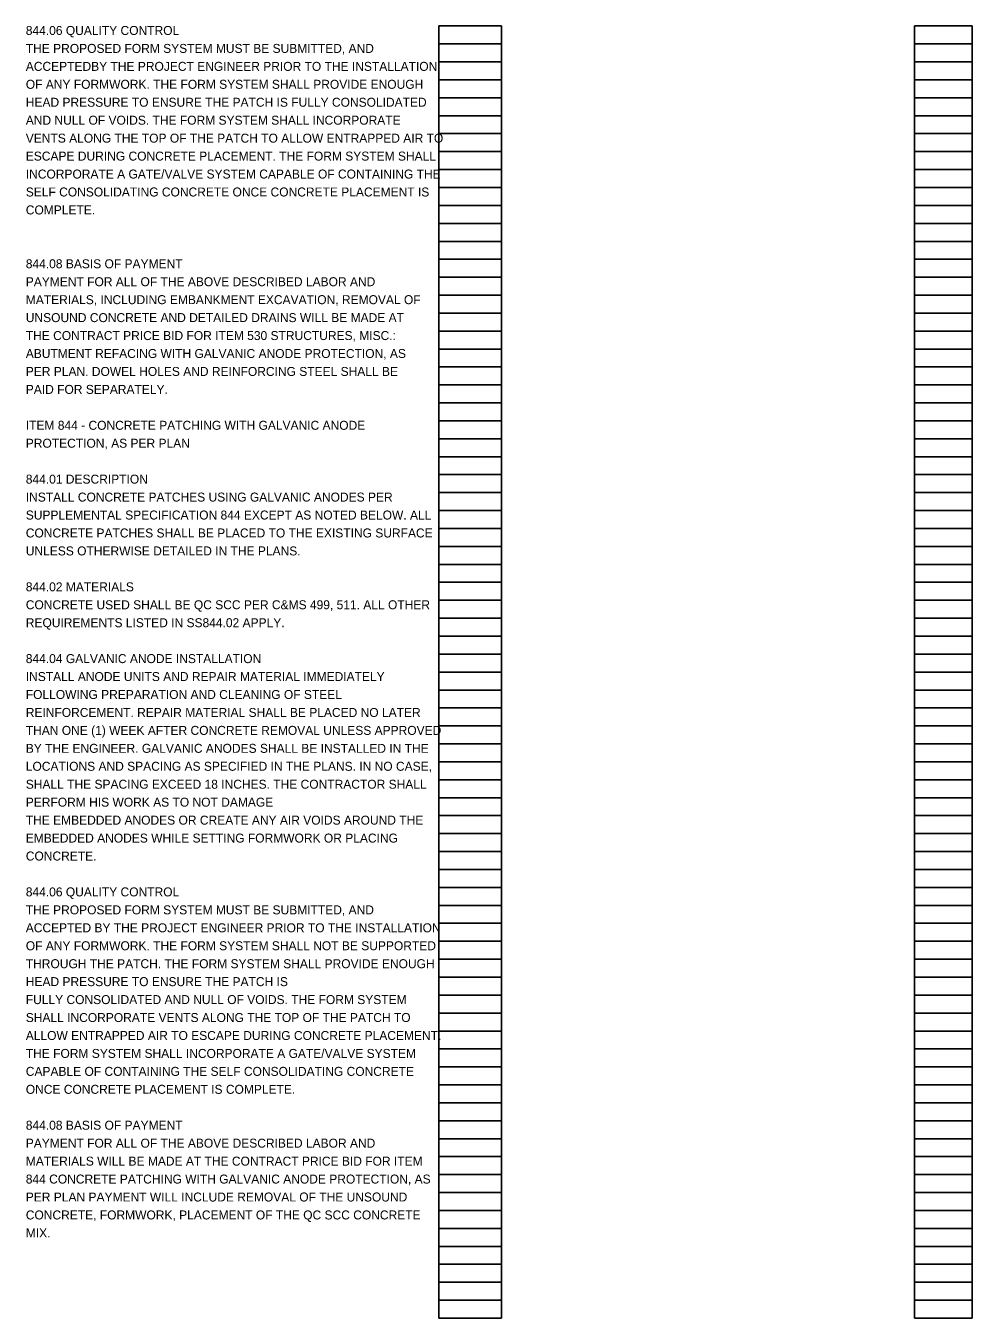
# Model space of a CAD drawing. Extents: x 0 to 66.4, y 0 to 28.8.
# Drawn here: x 51.65 to 66.41, y 0.98 to 21.14 of the extents above; entities that cross this region are included whole.
import ezdxf

# ---------------------------------------------------------------- set-up
doc = ezdxf.new("R2010")
doc.units = 0
doc.layers.add('SH_Data', color=7, linetype='Continuous')
doc.layers.add('SH_Text', color=7, linetype='Continuous')

msp = doc.modelspace()

# ---------------------------------------------------------------- linework, layer by layer
at = {"layer": 'SH_Data'}
for p, q in [((58.094, 0.98), (58.094, 21.14)), ((58.094, 21.14), (59.074, 21.14)), ((58.094, 0.98), (58.094, 21.14)), ((58.094, 21.14), (59.074, 21.14)), ((59.074, 0.98), (59.074, 21.14)), ((59.074, 0.98), (59.074, 21.14)), ((65.514, 0.98), (65.514, 21.14)), ((65.514, 21.14), (66.414, 21.14)), ((65.514, 0.98), (65.514, 21.14)), ((65.514, 21.14), (66.414, 21.14)), ((66.414, 0.98), (66.414, 21.14)), ((66.414, 0.98), (66.414, 21.14)), ((58.094, 20.86), (59.074, 20.86)), ((58.094, 20.86), (59.074, 20.86)), ((65.514, 20.86), (66.414, 20.86)), ((65.514, 20.86), (66.414, 20.86)), ((58.094, 20.58), (59.074, 20.58)), ((58.094, 20.58), (59.074, 20.58)), ((65.514, 20.58), (66.414, 20.58)), ((65.514, 20.58), (66.414, 20.58)), ((58.094, 20.3), (59.074, 20.3)), ((58.094, 20.3), (59.074, 20.3)), ((65.514, 20.3), (66.414, 20.3)), ((65.514, 20.3), (66.414, 20.3)), ((58.094, 20.02), (59.074, 20.02)), ((58.094, 20.02), (59.074, 20.02)), ((65.514, 20.02), (66.414, 20.02)), ((65.514, 20.02), (66.414, 20.02)), ((58.094, 19.74), (59.074, 19.74)), ((58.094, 19.74), (59.074, 19.74)), ((65.514, 19.74), (66.414, 19.74)), ((65.514, 19.74), (66.414, 19.74)), ((58.094, 19.46), (59.074, 19.46)), ((58.094, 19.46), (59.074, 19.46)), ((65.514, 19.46), (66.414, 19.46)), ((65.514, 19.46), (66.414, 19.46)), ((58.094, 19.18), (59.074, 19.18)), ((58.094, 19.18), (59.074, 19.18)), ((65.514, 19.18), (66.414, 19.18)), ((65.514, 19.18), (66.414, 19.18)), ((58.094, 18.9), (59.074, 18.9)), ((58.094, 18.9), (59.074, 18.9)), ((65.514, 18.9), (66.414, 18.9)), ((65.514, 18.9), (66.414, 18.9)), ((58.094, 18.62), (59.074, 18.62)), ((58.094, 18.62), (59.074, 18.62)), ((65.514, 18.62), (66.414, 18.62)), ((65.514, 18.62), (66.414, 18.62)), ((58.094, 18.34), (59.074, 18.34)), ((58.094, 18.34), (59.074, 18.34)), ((65.514, 18.34), (66.414, 18.34)), ((65.514, 18.34), (66.414, 18.34)), ((58.094, 18.06), (59.074, 18.06)), ((58.094, 18.06), (59.074, 18.06)), ((65.514, 18.06), (66.414, 18.06)), ((65.514, 18.06), (66.414, 18.06)), ((58.094, 17.78), (59.074, 17.78)), ((58.094, 17.78), (59.074, 17.78)), ((65.514, 17.78), (66.414, 17.78)), ((65.514, 17.78), (66.414, 17.78)), ((58.094, 17.5), (59.074, 17.5)), ((58.094, 17.5), (59.074, 17.5)), ((65.514, 17.5), (66.414, 17.5)), ((65.514, 17.5), (66.414, 17.5)), ((58.094, 17.22), (59.074, 17.22)), ((58.094, 17.22), (59.074, 17.22)), ((65.514, 17.22), (66.414, 17.22)), ((65.514, 17.22), (66.414, 17.22)), ((58.094, 16.94), (59.074, 16.94)), ((58.094, 16.94), (59.074, 16.94)), ((65.514, 16.94), (66.414, 16.94)), ((65.514, 16.94), (66.414, 16.94)), ((58.094, 16.66), (59.074, 16.66)), ((58.094, 16.66), (59.074, 16.66)), ((65.514, 16.66), (66.414, 16.66)), ((65.514, 16.66), (66.414, 16.66)), ((58.094, 16.38), (59.074, 16.38)), ((58.094, 16.38), (59.074, 16.38)), ((65.514, 16.38), (66.414, 16.38)), ((65.514, 16.38), (66.414, 16.38)), ((58.094, 16.1), (59.074, 16.1)), ((58.094, 16.1), (59.074, 16.1)), ((65.514, 16.1), (66.414, 16.1)), ((65.514, 16.1), (66.414, 16.1)), ((58.094, 15.82), (59.074, 15.82)), ((58.094, 15.82), (59.074, 15.82)), ((65.514, 15.82), (66.414, 15.82)), ((65.514, 15.82), (66.414, 15.82)), ((58.094, 15.54), (59.074, 15.54)), ((58.094, 15.54), (59.074, 15.54)), ((65.514, 15.54), (66.414, 15.54)), ((65.514, 15.54), (66.414, 15.54)), ((58.094, 15.26), (59.074, 15.26)), ((58.094, 15.26), (59.074, 15.26)), ((65.514, 15.26), (66.414, 15.26)), ((65.514, 15.26), (66.414, 15.26)), ((58.094, 14.98), (59.074, 14.98)), ((58.094, 14.98), (59.074, 14.98)), ((65.514, 14.98), (66.414, 14.98)), ((65.514, 14.98), (66.414, 14.98)), ((58.094, 14.7), (59.074, 14.7)), ((58.094, 14.7), (59.074, 14.7)), ((65.514, 14.7), (66.414, 14.7)), ((65.514, 14.7), (66.414, 14.7)), ((58.094, 14.42), (59.074, 14.42)), ((58.094, 14.42), (59.074, 14.42)), ((65.514, 14.42), (66.414, 14.42)), ((65.514, 14.42), (66.414, 14.42)), ((58.094, 14.14), (59.074, 14.14)), ((58.094, 14.14), (59.074, 14.14)), ((65.514, 14.14), (66.414, 14.14)), ((65.514, 14.14), (66.414, 14.14)), ((58.094, 13.86), (59.074, 13.86)), ((58.094, 13.86), (59.074, 13.86)), ((65.514, 13.86), (66.414, 13.86)), ((65.514, 13.86), (66.414, 13.86)), ((58.094, 13.58), (59.074, 13.58)), ((58.094, 13.58), (59.074, 13.58)), ((65.514, 13.58), (66.414, 13.58)), ((65.514, 13.58), (66.414, 13.58)), ((58.094, 13.3), (59.074, 13.3)), ((58.094, 13.3), (59.074, 13.3)), ((65.514, 13.3), (66.414, 13.3)), ((65.514, 13.3), (66.414, 13.3)), ((58.094, 13.02), (59.074, 13.02)), ((58.094, 13.02), (59.074, 13.02)), ((65.514, 13.02), (66.414, 13.02)), ((65.514, 13.02), (66.414, 13.02)), ((58.094, 12.74), (59.074, 12.74)), ((58.094, 12.74), (59.074, 12.74)), ((65.514, 12.74), (66.414, 12.74)), ((65.514, 12.74), (66.414, 12.74)), ((58.094, 12.46), (59.074, 12.46)), ((58.094, 12.46), (59.074, 12.46)), ((65.514, 12.46), (66.414, 12.46)), ((65.514, 12.46), (66.414, 12.46)), ((58.094, 12.18), (59.074, 12.18)), ((58.094, 12.18), (59.074, 12.18)), ((65.514, 12.18), (66.414, 12.18)), ((65.514, 12.18), (66.414, 12.18)), ((58.094, 11.9), (59.074, 11.9)), ((58.094, 11.9), (59.074, 11.9)), ((65.514, 11.9), (66.414, 11.9)), ((65.514, 11.9), (66.414, 11.9)), ((58.094, 11.62), (59.074, 11.62)), ((58.094, 11.62), (59.074, 11.62)), ((65.514, 11.62), (66.414, 11.62)), ((65.514, 11.62), (66.414, 11.62)), ((58.094, 11.34), (59.074, 11.34)), ((58.094, 11.34), (59.074, 11.34)), ((65.514, 11.34), (66.414, 11.34)), ((65.514, 11.34), (66.414, 11.34)), ((58.094, 11.06), (59.074, 11.06)), ((58.094, 11.06), (59.074, 11.06)), ((65.514, 11.06), (66.414, 11.06)), ((65.514, 11.06), (66.414, 11.06)), ((58.094, 10.78), (59.074, 10.78)), ((58.094, 10.78), (59.074, 10.78)), ((65.514, 10.78), (66.414, 10.78)), ((65.514, 10.78), (66.414, 10.78)), ((58.094, 10.5), (59.074, 10.5)), ((58.094, 10.5), (59.074, 10.5)), ((65.514, 10.5), (66.414, 10.5)), ((65.514, 10.5), (66.414, 10.5)), ((58.094, 10.22), (59.074, 10.22)), ((58.094, 10.22), (59.074, 10.22)), ((65.514, 10.22), (66.414, 10.22)), ((65.514, 10.22), (66.414, 10.22)), ((58.094, 9.94), (59.074, 9.94)), ((58.094, 9.94), (59.074, 9.94)), ((65.514, 9.94), (66.414, 9.94)), ((65.514, 9.94), (66.414, 9.94)), ((58.094, 9.66), (59.074, 9.66)), ((58.094, 9.66), (59.074, 9.66)), ((65.514, 9.66), (66.414, 9.66)), ((65.514, 9.66), (66.414, 9.66)), ((58.094, 9.38), (59.074, 9.38)), ((58.094, 9.38), (59.074, 9.38)), ((65.514, 9.38), (66.414, 9.38)), ((65.514, 9.38), (66.414, 9.38)), ((58.094, 9.1), (59.074, 9.1)), ((58.094, 9.1), (59.074, 9.1)), ((65.514, 9.1), (66.414, 9.1)), ((65.514, 9.1), (66.414, 9.1)), ((58.094, 8.82), (59.074, 8.82)), ((58.094, 8.82), (59.074, 8.82)), ((65.514, 8.82), (66.414, 8.82)), ((65.514, 8.82), (66.414, 8.82)), ((58.094, 8.54), (59.074, 8.54)), ((58.094, 8.54), (59.074, 8.54)), ((65.514, 8.54), (66.414, 8.54)), ((65.514, 8.54), (66.414, 8.54)), ((58.094, 8.26), (59.074, 8.26)), ((58.094, 8.26), (59.074, 8.26)), ((65.514, 8.26), (66.414, 8.26)), ((65.514, 8.26), (66.414, 8.26)), ((58.094, 7.98), (59.074, 7.98)), ((58.094, 7.98), (59.074, 7.98)), ((65.514, 7.98), (66.414, 7.98)), ((65.514, 7.98), (66.414, 7.98)), ((58.094, 7.7), (59.074, 7.7)), ((58.094, 7.7), (59.074, 7.7)), ((65.514, 7.7), (66.414, 7.7)), ((65.514, 7.7), (66.414, 7.7)), ((58.094, 7.42), (59.074, 7.42)), ((58.094, 7.42), (59.074, 7.42)), ((65.514, 7.42), (66.414, 7.42)), ((65.514, 7.42), (66.414, 7.42)), ((58.094, 7.14), (59.074, 7.14)), ((58.094, 7.14), (59.074, 7.14)), ((65.514, 7.14), (66.414, 7.14)), ((65.514, 7.14), (66.414, 7.14)), ((58.094, 6.86), (59.074, 6.86)), ((58.094, 6.86), (59.074, 6.86)), ((65.514, 6.86), (66.414, 6.86)), ((65.514, 6.86), (66.414, 6.86)), ((58.094, 6.58), (59.074, 6.58)), ((58.094, 6.58), (59.074, 6.58)), ((65.514, 6.58), (66.414, 6.58)), ((65.514, 6.58), (66.414, 6.58)), ((58.094, 6.3), (59.074, 6.3)), ((58.094, 6.3), (59.074, 6.3)), ((65.514, 6.3), (66.414, 6.3)), ((65.514, 6.3), (66.414, 6.3)), ((58.094, 6.02), (59.074, 6.02)), ((58.094, 6.02), (59.074, 6.02)), ((65.514, 6.02), (66.414, 6.02)), ((65.514, 6.02), (66.414, 6.02)), ((58.094, 5.74), (59.074, 5.74)), ((58.094, 5.74), (59.074, 5.74)), ((65.514, 5.74), (66.414, 5.74)), ((65.514, 5.74), (66.414, 5.74)), ((58.094, 5.46), (59.074, 5.46)), ((58.094, 5.46), (59.074, 5.46)), ((65.514, 5.46), (66.414, 5.46)), ((65.514, 5.46), (66.414, 5.46)), ((58.094, 5.18), (59.074, 5.18)), ((58.094, 5.18), (59.074, 5.18)), ((65.514, 5.18), (66.414, 5.18)), ((65.514, 5.18), (66.414, 5.18)), ((58.094, 4.9), (59.074, 4.9)), ((58.094, 4.9), (59.074, 4.9)), ((65.514, 4.9), (66.414, 4.9)), ((65.514, 4.9), (66.414, 4.9)), ((58.094, 4.62), (59.074, 4.62)), ((58.094, 4.62), (59.074, 4.62)), ((65.514, 4.62), (66.414, 4.62)), ((65.514, 4.62), (66.414, 4.62)), ((58.094, 4.34), (59.074, 4.34)), ((58.094, 4.34), (59.074, 4.34)), ((65.514, 4.34), (66.414, 4.34)), ((65.514, 4.34), (66.414, 4.34)), ((58.094, 4.06), (59.074, 4.06)), ((58.094, 4.06), (59.074, 4.06)), ((65.514, 4.06), (66.414, 4.06)), ((65.514, 4.06), (66.414, 4.06)), ((58.094, 3.78), (59.074, 3.78)), ((58.094, 3.78), (59.074, 3.78)), ((65.514, 3.78), (66.414, 3.78)), ((65.514, 3.78), (66.414, 3.78)), ((58.094, 3.5), (59.074, 3.5)), ((58.094, 3.5), (59.074, 3.5)), ((65.514, 3.5), (66.414, 3.5)), ((65.514, 3.5), (66.414, 3.5)), ((58.094, 3.22), (59.074, 3.22)), ((58.094, 3.22), (59.074, 3.22)), ((65.514, 3.22), (66.414, 3.22)), ((65.514, 3.22), (66.414, 3.22)), ((58.094, 2.94), (59.074, 2.94)), ((58.094, 2.94), (59.074, 2.94)), ((65.514, 2.94), (66.414, 2.94)), ((65.514, 2.94), (66.414, 2.94)), ((58.094, 2.66), (59.074, 2.66)), ((58.094, 2.66), (59.074, 2.66)), ((65.514, 2.66), (66.414, 2.66)), ((65.514, 2.66), (66.414, 2.66)), ((58.094, 2.38), (59.074, 2.38)), ((58.094, 2.38), (59.074, 2.38)), ((65.514, 2.38), (66.414, 2.38)), ((65.514, 2.38), (66.414, 2.38)), ((58.094, 2.1), (59.074, 2.1)), ((58.094, 2.1), (59.074, 2.1)), ((65.514, 2.1), (66.414, 2.1)), ((65.514, 2.1), (66.414, 2.1)), ((58.094, 1.82), (59.074, 1.82)), ((58.094, 1.82), (59.074, 1.82)), ((65.514, 1.82), (66.414, 1.82)), ((65.514, 1.82), (66.414, 1.82)), ((58.094, 1.54), (59.074, 1.54)), ((58.094, 1.54), (59.074, 1.54)), ((65.514, 1.54), (66.414, 1.54)), ((65.514, 1.54), (66.414, 1.54)), ((58.094, 1.26), (59.074, 1.26)), ((58.094, 1.26), (59.074, 1.26)), ((65.514, 1.26), (66.414, 1.26)), ((65.514, 1.26), (66.414, 1.26)), ((58.094, 0.98), (59.074, 0.98)), ((58.094, 0.98), (59.074, 0.98)), ((65.514, 0.98), (66.414, 0.98)), ((65.514, 0.98), (66.414, 0.98))]:
    msp.add_line(p, q, dxfattribs=at)

# ---------------------------------------------------------------- texts
at = {"layer": 'SH_Text'}
for s, p in [('844.06 QUALITY CONTROL', (51.654, 21)), ('THE PROPOSED FORM SYSTEM MUST BE SUBMITTED, AND', (51.654, 20.72)), ('ACCEPTEDBY THE PROJECT ENGINEER PRIOR TO THE INSTALLATION', (51.654, 20.44)), ('OF ANY FORMWORK. THE FORM SYSTEM SHALL PROVIDE ENOUGH', (51.654, 20.16)), ('HEAD PRESSURE TO ENSURE THE PATCH IS FULLY CONSOLIDATED', (51.654, 19.88)), ('AND NULL OF VOIDS. THE FORM SYSTEM SHALL INCORPORATE', (51.654, 19.6)), ('VENTS ALONG THE TOP OF THE PATCH TO ALLOW ENTRAPPED AIR TO', (51.654, 19.32)), ('ESCAPE DURING CONCRETE PLACEMENT. THE FORM SYSTEM SHALL', (51.654, 19.04)), ('INCORPORATE A GATE/VALVE SYSTEM CAPABLE OF CONTAINING THE', (51.654, 18.76)), ('SELF CONSOLIDATING CONCRETE ONCE CONCRETE PLACEMENT IS', (51.654, 18.48)), ('COMPLETE.', (51.654, 18.2)), ('844.08 BASIS OF PAYMENT', (51.654, 17.36)), ('PAYMENT FOR ALL OF THE ABOVE DESCRIBED LABOR AND', (51.654, 17.08)), ('MATERIALS, INCLUDING EMBANKMENT EXCAVATION, REMOVAL OF ', (51.654, 16.8)), ('UNSOUND CONCRETE AND DETAILED DRAINS WILL BE MADE AT', (51.654, 16.52)), ('THE CONTRACT PRICE BID FOR ITEM 530 STRUCTURES, MISC.: ', (51.654, 16.24)), ('ABUTMENT REFACING WITH GALVANIC ANODE PROTECTION, AS ', (51.654, 15.96)), ('PER PLAN. DOWEL HOLES AND REINFORCING STEEL SHALL BE ', (51.654, 15.68)), ('PAID FOR SEPARATELY.', (51.654, 15.4)), ('ITEM 844 - CONCRETE PATCHING WITH GALVANIC ANODE', (51.654, 14.84)), ('PROTECTION, AS PER PLAN', (51.654, 14.56)), ('844.01 DESCRIPTION', (51.654, 14)), ('INSTALL CONCRETE PATCHES USING GALVANIC ANODES PER', (51.654, 13.72)), ('SUPPLEMENTAL SPECIFICATION 844 EXCEPT AS NOTED BELOW. ALL', (51.654, 13.44)), ('CONCRETE PATCHES SHALL BE PLACED TO THE EXISTING SURFACE', (51.654, 13.16)), ('UNLESS OTHERWISE DETAILED IN THE PLANS.', (51.654, 12.88)), ('844.02 MATERIALS', (51.654, 12.32)), ('CONCRETE USED SHALL BE QC SCC PER C&MS 499, 511. ALL OTHER', (51.654, 12.04)), ('REQUIREMENTS LISTED IN SS844.02 APPLY.', (51.654, 11.76)), ('844.04 GALVANIC ANODE INSTALLATION', (51.654, 11.2)), ('INSTALL ANODE UNITS AND REPAIR MATERIAL IMMEDIATELY', (51.654, 10.92)), ('FOLLOWING PREPARATION AND CLEANING OF STEEL', (51.654, 10.64)), ('REINFORCEMENT. REPAIR MATERIAL SHALL BE PLACED NO LATER', (51.654, 10.36)), ('THAN ONE (1) WEEK AFTER CONCRETE REMOVAL UNLESS APPROVED', (51.654, 10.08)), ('BY THE ENGINEER. GALVANIC ANODES SHALL BE INSTALLED IN THE', (51.654, 9.8)), ('LOCATIONS AND SPACING AS SPECIFIED IN THE PLANS. IN NO CASE,', (51.654, 9.52)), ('SHALL THE SPACING EXCEED 18 INCHES. THE CONTRACTOR SHALL', (51.654, 9.24)), ('PERFORM HIS WORK AS TO NOT DAMAGE', (51.654, 8.96)), ('THE EMBEDDED ANODES OR CREATE ANY AIR VOIDS AROUND THE', (51.654, 8.68)), ('EMBEDDED ANODES WHILE SETTING FORMWORK OR PLACING', (51.654, 8.4)), ('CONCRETE.', (51.654, 8.12)), ('844.06 QUALITY CONTROL', (51.654, 7.56)), ('THE PROPOSED FORM SYSTEM MUST BE SUBMITTED, AND', (51.654, 7.28)), ('ACCEPTED BY THE PROJECT ENGINEER PRIOR TO THE INSTALLATION', (51.654, 7)), ('OF ANY FORMWORK. THE FORM SYSTEM SHALL NOT BE SUPPORTED', (51.654, 6.72)), ('THROUGH THE PATCH. THE FORM SYSTEM SHALL PROVIDE ENOUGH', (51.654, 6.44)), ('HEAD PRESSURE TO ENSURE THE PATCH IS', (51.654, 6.16)), ('FULLY CONSOLIDATED AND NULL OF VOIDS. THE FORM SYSTEM', (51.654, 5.88)), ('SHALL INCORPORATE VENTS ALONG THE TOP OF THE PATCH TO', (51.654, 5.6)), ('ALLOW ENTRAPPED AIR TO ESCAPE DURING CONCRETE PLACEMENT.', (51.654, 5.32)), ('THE FORM SYSTEM SHALL INCORPORATE A GATE/VALVE SYSTEM', (51.654, 5.04)), ('CAPABLE OF CONTAINING THE SELF CONSOLIDATING CONCRETE', (51.654, 4.76)), ('ONCE CONCRETE PLACEMENT IS COMPLETE.', (51.654, 4.48)), ('844.08 BASIS OF PAYMENT', (51.654, 3.92)), ('PAYMENT FOR ALL OF THE ABOVE DESCRIBED LABOR AND', (51.654, 3.64)), ('MATERIALS WILL BE MADE AT THE CONTRACT PRICE BID FOR ITEM', (51.654, 3.36)), ('844 CONCRETE PATCHING WITH GALVANIC ANODE PROTECTION, AS', (51.654, 3.08)), ('PER PLAN PAYMENT WILL INCLUDE REMOVAL OF THE UNSOUND', (51.654, 2.8)), ('CONCRETE, FORMWORK, PLACEMENT OF THE QC SCC CONCRETE', (51.654, 2.52)), ('MIX.', (51.654, 2.24))]:
    msp.add_text(s, height=0.14, dxfattribs=at).set_placement(p)

doc.saveas('drawing.dxf')
